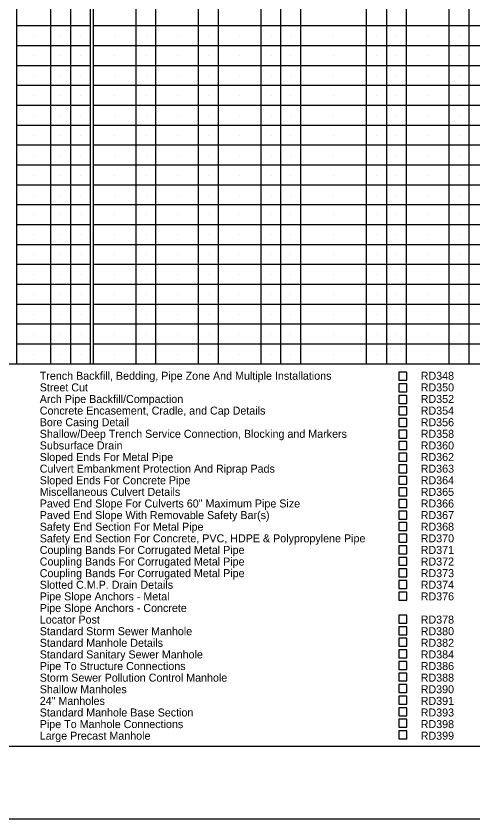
# Model space of a CAD drawing. Extents: x -1700 to 0, y 0 to 1100.
# Drawn here: x -1087 to -773, y 0 to 551 of the extents above; entities that cross this region are included whole.
import ezdxf

# ---------------------------------------------------------------- set-up
doc = ezdxf.new("R2010")
doc.units = 0
for name, color, linetype in [('#plot_shape', 7, 'Continuous'), ('P_ODOT_PLAN_Border', 7, 'Continuous'), ('P_ODOT_PLAN_General', 7, 'Continuous'), ('P_RDWY_PLAN_NotesTx', 7, 'Continuous')]:
    doc.layers.add(name, color=color, linetype=linetype)

msp = doc.modelspace()

# ---------------------------------------------------------------- linework, layer by layer
at = {"layer": '#plot_shape'}
msp.add_lwpolyline([(-1700, 0), (0, 0), (0, 1100), (-1700, 1100)], close=True, dxfattribs=at)
at = {"layer": 'P_ODOT_PLAN_Border'}
msp.add_lwpolyline([(-1625, 50), (-25, 50), (-25, 1050), (-1625, 1050)], close=True, dxfattribs=at)
at = {"layer": 'P_ODOT_PLAN_General'}
for p, q in [((-1086.47, 312.45), (-1086.47, 1050)), ((-1035.74, 312.45), (-1035.74, 1050)), ((-1033.79, 312.45), (-1033.79, 1050)), ((-818.78, 312.45), (-818.78, 1023.66)), ((-1049.39, 312.45), (-1049.39, 1010.98)), ((-891.35, 312.45), (-891.35, 998.29)), ((-990.86, 312.45), (-990.86, 985.61)), ((-947.93, 312.45), (-947.93, 985.61)), ((-846.35, 312.45), (-846.35, 985.61)), ((-832.44, 312.45), (-832.44, 985.61)), ((-775.85, 312.45), (-775.85, 985.61)), ((-1004.52, 312.45), (-1004.52, 973.9)), ((-961.59, 312.45), (-961.59, 973.9)), ((-918.66, 312.45), (-918.66, 973.9)), ((-905.01, 312.45), (-905.01, 973.9)), ((-789.51, 312.45), (-789.51, 973.9)), ((-1063.05, 312.45), (-1063.05, 913.42)), ((-1035.74, 544.64), (-1086.47, 544.64)), ((-392.85, 544.64), (-1033.79, 544.64)), ((-1074.76, 537.81), (-1074.76, 537.81)), ((-1056.22, 537.81), (-1056.22, 537.81)), ((-1042.57, 537.81), (-1042.57, 537.81)), ((-1019.15, 537.81), (-1019.15, 537.81)), ((-997.69, 537.81), (-997.69, 537.81)), ((-976.22, 537.81), (-976.22, 537.81)), ((-954.76, 537.81), (-954.76, 537.81)), ((-933.3, 537.81), (-933.3, 537.81)), ((-911.84, 537.81), (-911.84, 537.81)), ((-898.18, 537.81), (-898.18, 537.81)), ((-868.85, 537.81), (-868.85, 537.81)), ((-839.27, 537.81), (-839.27, 537.81)), ((-825.61, 537.81), (-825.61, 537.81)), ((-804.15, 537.81), (-804.15, 537.81)), ((-782.68, 537.81), (-782.68, 537.81)), ((-1035.74, 530.98), (-1086.47, 530.98)), ((-392.85, 530.98), (-1033.79, 530.98)), ((-1074.76, 524.15), (-1074.76, 524.15)), ((-1056.22, 524.15), (-1056.22, 524.15)), ((-1042.57, 524.15), (-1042.57, 524.15)), ((-1019.15, 524.15), (-1019.15, 524.15)), ((-997.69, 524.15), (-997.69, 524.15)), ((-976.22, 524.15), (-976.22, 524.15)), ((-954.76, 524.15), (-954.76, 524.15)), ((-933.3, 524.15), (-933.3, 524.15)), ((-911.84, 524.15), (-911.84, 524.15)), ((-898.18, 524.15), (-898.18, 524.15)), ((-868.85, 524.15), (-868.85, 524.15)), ((-839.27, 524.15), (-839.27, 524.15)), ((-825.61, 524.15), (-825.61, 524.15)), ((-804.15, 524.15), (-804.15, 524.15)), ((-782.68, 524.15), (-782.68, 524.15)), ((-1035.74, 517.32), (-1086.47, 517.32)), ((-392.85, 517.32), (-1033.79, 517.32)), ((-1074.76, 510.49), (-1074.76, 510.49)), ((-1056.22, 510.49), (-1056.22, 510.49)), ((-1042.57, 510.49), (-1042.57, 510.49)), ((-1019.15, 510.49), (-1019.15, 510.49)), ((-997.69, 510.49), (-997.69, 510.49)), ((-976.22, 510.49), (-976.22, 510.49)), ((-954.76, 510.49), (-954.76, 510.49)), ((-933.3, 510.49), (-933.3, 510.49)), ((-911.84, 510.49), (-911.84, 510.49)), ((-898.18, 510.49), (-898.18, 510.49)), ((-868.85, 510.49), (-868.85, 510.49)), ((-839.27, 510.49), (-839.27, 510.49)), ((-825.61, 510.49), (-825.61, 510.49)), ((-804.15, 510.49), (-804.15, 510.49)), ((-782.68, 510.49), (-782.68, 510.49)), ((-1035.74, 503.66), (-1086.47, 503.66)), ((-392.85, 503.66), (-1033.79, 503.66)), ((-1074.76, 496.83), (-1074.76, 496.83)), ((-1056.22, 496.83), (-1056.22, 496.83)), ((-1042.57, 496.83), (-1042.57, 496.83)), ((-1019.15, 496.83), (-1019.15, 496.83)), ((-997.69, 496.83), (-997.69, 496.83)), ((-976.22, 496.83), (-976.22, 496.83)), ((-954.76, 496.83), (-954.76, 496.83)), ((-933.3, 496.83), (-933.3, 496.83)), ((-911.84, 496.83), (-911.84, 496.83)), ((-898.18, 496.83), (-898.18, 496.83)), ((-868.85, 496.83), (-868.85, 496.83)), ((-839.27, 496.83), (-839.27, 496.83)), ((-825.61, 496.83), (-825.61, 496.83)), ((-804.15, 496.83), (-804.15, 496.83)), ((-782.68, 496.83), (-782.68, 496.83)), ((-1035.74, 490.01), (-1086.47, 490.01)), ((-392.85, 490.01), (-1033.79, 490.01)), ((-1074.76, 483.18), (-1074.76, 483.18)), ((-1056.22, 483.18), (-1056.22, 483.18)), ((-1042.57, 483.18), (-1042.57, 483.18)), ((-1019.15, 483.18), (-1019.15, 483.18)), ((-997.69, 483.18), (-997.69, 483.18)), ((-976.22, 483.18), (-976.22, 483.18)), ((-954.76, 483.18), (-954.76, 483.18)), ((-933.3, 483.18), (-933.3, 483.18)), ((-911.84, 483.18), (-911.84, 483.18)), ((-898.18, 483.18), (-898.18, 483.18)), ((-868.85, 483.18), (-868.85, 483.18)), ((-839.27, 483.18), (-839.27, 483.18)), ((-825.61, 483.18), (-825.61, 483.18)), ((-804.15, 483.18), (-804.15, 483.18)), ((-782.68, 483.18), (-782.68, 483.18)), ((-1035.74, 476.35), (-1086.47, 476.35)), ((-392.85, 476.35), (-1033.79, 476.35)), ((-1074.76, 469.52), (-1074.76, 469.52)), ((-1056.22, 469.52), (-1056.22, 469.52)), ((-1042.57, 469.52), (-1042.57, 469.52)), ((-1019.15, 469.52), (-1019.15, 469.52)), ((-997.69, 469.52), (-997.69, 469.52)), ((-976.22, 469.52), (-976.22, 469.52)), ((-954.76, 469.52), (-954.76, 469.52)), ((-933.3, 469.52), (-933.3, 469.52)), ((-911.84, 469.52), (-911.84, 469.52)), ((-898.18, 469.52), (-898.18, 469.52)), ((-868.85, 469.52), (-868.85, 469.52)), ((-839.27, 469.52), (-839.27, 469.52)), ((-825.61, 469.52), (-825.61, 469.52)), ((-804.15, 469.52), (-804.15, 469.52)), ((-782.68, 469.52), (-782.68, 469.52)), ((-1035.74, 462.69), (-1086.47, 462.69)), ((-392.85, 462.69), (-1033.79, 462.69)), ((-1074.76, 455.86), (-1074.76, 455.86)), ((-1056.22, 455.86), (-1056.22, 455.86)), ((-1042.57, 455.86), (-1042.57, 455.86)), ((-1019.15, 455.86), (-1019.15, 455.86)), ((-997.69, 455.86), (-997.69, 455.86)), ((-976.22, 455.86), (-976.22, 455.86)), ((-954.76, 455.86), (-954.76, 455.86)), ((-933.3, 455.86), (-933.3, 455.86)), ((-911.84, 455.86), (-911.84, 455.86)), ((-898.18, 455.86), (-898.18, 455.86)), ((-868.85, 455.86), (-868.85, 455.86)), ((-839.27, 455.86), (-839.27, 455.86)), ((-825.61, 455.86), (-825.61, 455.86)), ((-804.15, 455.86), (-804.15, 455.86)), ((-782.68, 455.86), (-782.68, 455.86)), ((-1035.74, 449.03), (-1086.47, 449.03)), ((-392.85, 449.03), (-1033.79, 449.03)), ((-1074.76, 442.2), (-1074.76, 442.2)), ((-1056.22, 442.2), (-1056.22, 442.2)), ((-1042.57, 442.2), (-1042.57, 442.2)), ((-1019.15, 442.2), (-1019.15, 442.2)), ((-997.69, 442.2), (-997.69, 442.2)), ((-976.22, 442.2), (-976.22, 442.2)), ((-954.76, 442.2), (-954.76, 442.2)), ((-933.3, 442.2), (-933.3, 442.2)), ((-911.84, 442.2), (-911.84, 442.2)), ((-898.18, 442.2), (-898.18, 442.2)), ((-868.85, 442.2), (-868.85, 442.2)), ((-839.27, 442.2), (-839.27, 442.2)), ((-825.61, 442.2), (-825.61, 442.2)), ((-804.15, 442.2), (-804.15, 442.2)), ((-782.68, 442.2), (-782.68, 442.2)), ((-1035.74, 435.37), (-1086.47, 435.37)), ((-392.85, 435.37), (-1033.79, 435.37)), ((-1074.76, 428.54), (-1074.76, 428.54)), ((-1056.22, 428.54), (-1056.22, 428.54)), ((-1042.57, 428.54), (-1042.57, 428.54)), ((-1019.15, 428.54), (-1019.15, 428.54)), ((-997.69, 428.54), (-997.69, 428.54)), ((-976.22, 428.54), (-976.22, 428.54)), ((-954.76, 428.54), (-954.76, 428.54)), ((-933.3, 428.54), (-933.3, 428.54)), ((-911.84, 428.54), (-911.84, 428.54)), ((-898.18, 428.54), (-898.18, 428.54)), ((-868.85, 428.54), (-868.85, 428.54)), ((-839.27, 428.54), (-839.27, 428.54)), ((-825.61, 428.54), (-825.61, 428.54)), ((-804.15, 428.54), (-804.15, 428.54)), ((-782.68, 428.54), (-782.68, 428.54)), ((-1035.74, 421.71), (-1086.47, 421.71)), ((-392.85, 421.71), (-1033.79, 421.71)), ((-1074.76, 414.88), (-1074.76, 414.88)), ((-1056.22, 414.88), (-1056.22, 414.88)), ((-1042.57, 414.88), (-1042.57, 414.88)), ((-1019.15, 414.88), (-1019.15, 414.88)), ((-997.69, 414.88), (-997.69, 414.88)), ((-976.22, 414.88), (-976.22, 414.88)), ((-954.76, 414.88), (-954.76, 414.88)), ((-933.3, 414.88), (-933.3, 414.88)), ((-911.84, 414.88), (-911.84, 414.88)), ((-898.18, 414.88), (-898.18, 414.88)), ((-868.85, 414.88), (-868.85, 414.88)), ((-839.27, 414.88), (-839.27, 414.88)), ((-825.61, 414.88), (-825.61, 414.88)), ((-804.15, 414.88), (-804.15, 414.88)), ((-782.68, 414.88), (-782.68, 414.88)), ((-1035.74, 408.06), (-1086.47, 408.06)), ((-392.85, 408.06), (-1033.79, 408.06)), ((-1074.76, 401.23), (-1074.76, 401.23)), ((-1056.22, 401.23), (-1056.22, 401.23)), ((-1042.57, 401.23), (-1042.57, 401.23)), ((-1019.15, 401.23), (-1019.15, 401.23)), ((-997.69, 401.23), (-997.69, 401.23)), ((-976.22, 401.23), (-976.22, 401.23)), ((-954.76, 401.23), (-954.76, 401.23)), ((-933.3, 401.23), (-933.3, 401.23)), ((-911.84, 401.23), (-911.84, 401.23)), ((-898.18, 401.23), (-898.18, 401.23)), ((-868.85, 401.23), (-868.85, 401.23)), ((-839.27, 401.23), (-839.27, 401.23)), ((-825.61, 401.23), (-825.61, 401.23)), ((-804.15, 401.23), (-804.15, 401.23)), ((-782.68, 401.23), (-782.68, 401.23)), ((-1035.74, 394.4), (-1086.47, 394.4)), ((-392.85, 394.4), (-1033.79, 394.4)), ((-1074.76, 387.57), (-1074.76, 387.57)), ((-1056.22, 387.57), (-1056.22, 387.57)), ((-1042.57, 387.57), (-1042.57, 387.57)), ((-1019.15, 387.57), (-1019.15, 387.57)), ((-997.69, 387.57), (-997.69, 387.57)), ((-976.22, 387.57), (-976.22, 387.57)), ((-954.76, 387.57), (-954.76, 387.57)), ((-933.3, 387.57), (-933.3, 387.57)), ((-911.84, 387.57), (-911.84, 387.57)), ((-898.18, 387.57), (-898.18, 387.57)), ((-868.85, 387.57), (-868.85, 387.57)), ((-839.27, 387.57), (-839.27, 387.57)), ((-825.61, 387.57), (-825.61, 387.57)), ((-804.15, 387.57), (-804.15, 387.57)), ((-782.68, 387.57), (-782.68, 387.57)), ((-1035.74, 380.74), (-1086.47, 380.74)), ((-392.85, 380.74), (-1033.79, 380.74)), ((-1074.76, 373.91), (-1074.76, 373.91)), ((-1056.22, 373.91), (-1056.22, 373.91)), ((-1042.57, 373.91), (-1042.57, 373.91)), ((-1019.15, 373.91), (-1019.15, 373.91)), ((-997.69, 373.91), (-997.69, 373.91)), ((-976.22, 373.91), (-976.22, 373.91)), ((-954.76, 373.91), (-954.76, 373.91)), ((-933.3, 373.91), (-933.3, 373.91)), ((-911.84, 373.91), (-911.84, 373.91)), ((-898.18, 373.91), (-898.18, 373.91)), ((-868.85, 373.91), (-868.85, 373.91)), ((-839.27, 373.91), (-839.27, 373.91)), ((-825.61, 373.91), (-825.61, 373.91)), ((-804.15, 373.91), (-804.15, 373.91)), ((-782.68, 373.91), (-782.68, 373.91)), ((-1035.74, 367.08), (-1086.47, 367.08)), ((-392.85, 367.08), (-1033.79, 367.08)), ((-1074.76, 360.25), (-1074.76, 360.25)), ((-1056.22, 360.25), (-1056.22, 360.25)), ((-1042.57, 360.25), (-1042.57, 360.25)), ((-1019.15, 360.25), (-1019.15, 360.25)), ((-997.69, 360.25), (-997.69, 360.25)), ((-976.22, 360.25), (-976.22, 360.25)), ((-954.76, 360.25), (-954.76, 360.25)), ((-933.3, 360.25), (-933.3, 360.25)), ((-911.84, 360.25), (-911.84, 360.25)), ((-898.18, 360.25), (-898.18, 360.25)), ((-868.85, 360.25), (-868.85, 360.25)), ((-839.27, 360.25), (-839.27, 360.25)), ((-825.61, 360.25), (-825.61, 360.25)), ((-804.15, 360.25), (-804.15, 360.25)), ((-782.68, 360.25), (-782.68, 360.25)), ((-1035.74, 353.42), (-1086.47, 353.42)), ((-392.85, 353.42), (-1033.79, 353.42)), ((-1074.76, 346.59), (-1074.76, 346.59)), ((-1056.22, 346.59), (-1056.22, 346.59)), ((-1042.57, 346.59), (-1042.57, 346.59)), ((-1019.15, 346.59), (-1019.15, 346.59)), ((-997.69, 346.59), (-997.69, 346.59)), ((-976.22, 346.59), (-976.22, 346.59)), ((-954.76, 346.59), (-954.76, 346.59)), ((-933.3, 346.59), (-933.3, 346.59)), ((-911.84, 346.59), (-911.84, 346.59)), ((-898.18, 346.59), (-898.18, 346.59)), ((-868.85, 346.59), (-868.85, 346.59)), ((-839.27, 346.59), (-839.27, 346.59)), ((-825.61, 346.59), (-825.61, 346.59)), ((-804.15, 346.59), (-804.15, 346.59)), ((-782.68, 346.59), (-782.68, 346.59)), ((-1035.74, 339.76), (-1086.47, 339.76)), ((-392.85, 339.76), (-1033.79, 339.76)), ((-1074.76, 332.93), (-1074.76, 332.93)), ((-1056.22, 332.93), (-1056.22, 332.93)), ((-1042.57, 332.93), (-1042.57, 332.93)), ((-1019.15, 332.93), (-1019.15, 332.93)), ((-997.69, 332.93), (-997.69, 332.93)), ((-976.22, 332.93), (-976.22, 332.93)), ((-954.76, 332.93), (-954.76, 332.93)), ((-933.3, 332.93), (-933.3, 332.93)), ((-911.84, 332.93), (-911.84, 332.93)), ((-898.18, 332.93), (-898.18, 332.93)), ((-868.85, 332.93), (-868.85, 332.93)), ((-839.27, 332.93), (-839.27, 332.93)), ((-825.61, 332.93), (-825.61, 332.93)), ((-804.15, 332.93), (-804.15, 332.93)), ((-782.68, 332.93), (-782.68, 332.93)), ((-1035.74, 326.1), (-1086.47, 326.1)), ((-392.85, 326.1), (-1033.79, 326.1)), ((-1074.76, 319.28), (-1074.76, 319.28)), ((-1056.22, 319.28), (-1056.22, 319.28)), ((-1042.57, 319.28), (-1042.57, 319.28)), ((-1019.15, 319.28), (-1019.15, 319.28)), ((-997.69, 319.28), (-997.69, 319.28)), ((-976.22, 319.28), (-976.22, 319.28)), ((-954.76, 319.28), (-954.76, 319.28)), ((-933.3, 319.28), (-933.3, 319.28)), ((-911.84, 319.28), (-911.84, 319.28)), ((-898.18, 319.28), (-898.18, 319.28)), ((-868.85, 319.28), (-868.85, 319.28)), ((-839.27, 319.28), (-839.27, 319.28)), ((-825.61, 319.28), (-825.61, 319.28)), ((-804.15, 319.28), (-804.15, 319.28)), ((-782.68, 319.28), (-782.68, 319.28)), ((-25.02, 312.45), (-1625, 312.45))]:
    msp.add_line(p, q, dxfattribs=at)
at = {"layer": 'P_RDWY_PLAN_NotesTx'}
for points in [[(-818.69, 306.81), (-824.16, 306.81), (-824.16, 301.34), (-818.69, 301.34)], [(-818.69, 298.86), (-824.16, 298.86), (-824.16, 293.39), (-818.69, 293.39)], [(-818.69, 290.92), (-824.16, 290.92), (-824.16, 285.45), (-818.69, 285.45)], [(-818.69, 282.97), (-824.16, 282.97), (-824.16, 277.5), (-818.69, 277.5)], [(-818.69, 275.03), (-824.16, 275.03), (-824.16, 269.56), (-818.69, 269.56)], [(-818.69, 267.08), (-824.16, 267.08), (-824.16, 261.61), (-818.69, 261.61)], [(-818.69, 259.14), (-824.16, 259.14), (-824.16, 253.67), (-818.69, 253.67)], [(-818.69, 251.19), (-824.16, 251.19), (-824.16, 245.72), (-818.69, 245.72)], [(-818.69, 243.25), (-824.16, 243.25), (-824.16, 237.78), (-818.69, 237.78)], [(-818.69, 235.3), (-824.16, 235.3), (-824.16, 229.83), (-818.69, 229.83)], [(-818.69, 227.35), (-824.16, 227.35), (-824.16, 221.88), (-818.69, 221.88)], [(-818.69, 219.41), (-824.16, 219.41), (-824.16, 213.94), (-818.69, 213.94)], [(-818.69, 211.46), (-824.16, 211.46), (-824.16, 205.99), (-818.69, 205.99)], [(-818.69, 203.52), (-824.16, 203.52), (-824.16, 198.05), (-818.69, 198.05)], [(-818.69, 195.57), (-824.16, 195.57), (-824.16, 190.1), (-818.69, 190.1)], [(-818.69, 187.63), (-824.16, 187.63), (-824.16, 182.16), (-818.69, 182.16)], [(-818.69, 179.68), (-824.16, 179.68), (-824.16, 174.21), (-818.69, 174.21)], [(-818.69, 171.74), (-824.16, 171.74), (-824.16, 166.27), (-818.69, 166.27)], [(-818.69, 163.79), (-824.16, 163.79), (-824.16, 158.32), (-818.69, 158.32)], [(-818.69, 155.85), (-824.16, 155.85), (-824.16, 150.38), (-818.69, 150.38)], [(-818.69, 139.96), (-824.16, 139.96), (-824.16, 134.49), (-818.69, 134.49)], [(-818.69, 132.01), (-824.16, 132.01), (-824.16, 126.54), (-818.69, 126.54)], [(-818.69, 124.07), (-824.16, 124.07), (-824.16, 118.6), (-818.69, 118.6)], [(-818.69, 116.12), (-824.16, 116.12), (-824.16, 110.65), (-818.69, 110.65)], [(-818.69, 108.18), (-824.16, 108.18), (-824.16, 102.71), (-818.69, 102.71)], [(-818.69, 100.23), (-824.16, 100.23), (-824.16, 94.76), (-818.69, 94.76)], [(-818.69, 92.29), (-824.16, 92.29), (-824.16, 86.82), (-818.69, 86.82)], [(-818.69, 84.34), (-824.16, 84.34), (-824.16, 78.87), (-818.69, 78.87)], [(-818.69, 76.39), (-824.16, 76.39), (-824.16, 70.92), (-818.69, 70.92)], [(-818.69, 68.45), (-824.16, 68.45), (-824.16, 62.98), (-818.69, 62.98)], [(-818.69, 60.5), (-824.16, 60.5), (-824.16, 55.03), (-818.69, 55.03)]]:
    msp.add_lwpolyline(points, close=True, dxfattribs=at)

# ---------------------------------------------------------------- texts
for s, p in [('Trench Backfill, Bedding, Pipe Zone And Multiple Installations', (-1070.66, 301.65)), ('RD348', (-809.07, 301.65)), ('Street Cut', (-1070.66, 293.67)), ('RD350', (-809.07, 293.67)), ('Arch Pipe Backfill/Compaction', (-1070.66, 285.7)), ('RD352', (-809.07, 285.7)), ('Concrete Encasement, Cradle, and Cap Details', (-1070.66, 277.72)), ('RD354', (-809.07, 277.72)), ('Bore Casing Detail', (-1070.66, 269.75)), ('RD356', (-809.07, 269.75)), ('Shallow/Deep Trench Service Connection, Blocking and Markers', (-1070.66, 261.77)), ('RD358', (-809.07, 261.77)), ('Subsurface Drain', (-1070.66, 253.8)), ('RD360', (-809.07, 253.8)), ('Sloped Ends For Metal Pipe', (-1070.66, 245.82)), ('RD362', (-809.07, 245.82)), ('Culvert Embankment Protection And Riprap Pads', (-1070.66, 237.85)), ('RD363', (-809.07, 237.85)), ('Sloped Ends For Concrete Pipe', (-1070.66, 229.87)), ('RD364', (-809.07, 229.87)), ('Miscellaneous Culvert Details', (-1070.66, 221.9)), ('RD365', (-809.07, 221.9)), ('Paved End Slope For Culverts 60" Maximum Pipe Size ', (-1070.66, 213.92)), ('RD366', (-809.07, 213.92)), ('Paved End Slope With Removable Safety Bar(s)', (-1070.66, 205.95)), ('RD367', (-809.07, 205.95)), ('Safety End Section For Metal Pipe', (-1070.66, 197.97)), ('RD368', (-809.07, 197.97)), ('Safety End Section For Concrete, PVC, HDPE & Polypropylene Pipe', (-1070.66, 190)), ('RD370', (-809.07, 190)), ('Coupling Bands For Corrugated Metal Pipe', (-1070.66, 182.02)), ('RD371', (-809.07, 182.02)), ('Coupling Bands For Corrugated Metal Pipe', (-1070.66, 174.05)), ('RD372', (-809.07, 174.05)), ('Coupling Bands For Corrugated Metal Pipe', (-1070.66, 166.07)), ('RD373', (-809.07, 166.07)), ('Slotted C.M.P. Drain Details', (-1070.66, 158.1)), ('RD374', (-809.07, 158.1)), ('Pipe Slope Anchors - Metal ', (-1070.66, 150.12)), ('RD376', (-809.07, 150.12)), ('Pipe Slope Anchors - Concrete', (-1070.66, 142.15)), ('Locator Post', (-1070.66, 134.17)), ('RD378', (-809.07, 134.17)), ('Standard Storm Sewer Manhole', (-1070.66, 126.2)), ('RD380', (-809.07, 126.2)), ('Standard Manhole Details', (-1070.66, 118.22)), ('RD382', (-809.07, 118.22)), ('Standard Sanitary Sewer Manhole', (-1070.66, 110.25)), ('RD384', (-809.07, 110.25)), ('Pipe To Structure Connections', (-1070.66, 102.27)), ('RD386', (-809.07, 102.27)), ('Storm Sewer Pollution Control Manhole', (-1070.66, 94.3)), ('RD388', (-809.07, 94.3)), ('Shallow Manholes', (-1070.66, 86.32)), ('RD390', (-809.07, 86.32)), ('24" Manholes', (-1070.66, 78.35)), ('RD391', (-809.07, 78.35)), ('Standard Manhole Base Section', (-1070.66, 70.37)), ('RD393', (-809.07, 70.37)), ('Pipe To Manhole Connections', (-1070.66, 62.4)), ('RD398', (-809.07, 62.4)), ('Large Precast Manhole', (-1070.66, 54.42)), ('RD399', (-809.07, 54.42))]:
    msp.add_text(s, height=5.5, dxfattribs=at).set_placement(p)

doc.saveas('drawing.dxf')
